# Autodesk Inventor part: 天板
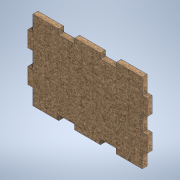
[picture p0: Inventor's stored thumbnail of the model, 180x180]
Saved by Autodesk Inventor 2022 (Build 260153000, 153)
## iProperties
Created: 2024-11
Part Number: 天板
Material: MDF 中密度繊維ボード
Document SubType Name: Modeling
Designer: shimizu
Density: 0.8 g/cm^3
Appearance: ダンボール - 段ボール紙
Author: shimizu
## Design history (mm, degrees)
sketch "スケッチ1"
  geometry: L1 (-25.119, 2.566)-(-27.619, 2.566); L2 (-27.619, 2.566)-(-27.619, -5.434); L3 (-27.619, -5.434)-(-25.119, -5.434); L4 (-25.119, -13.434)-(-27.619, -13.434); L5 (-27.619, -13.434)-(-27.619, -21.434); L6 (-27.619, -21.434)-(-25.119, -21.434); L7 (29.881, 2.566)-(32.381, 2.566); L8 (32.381, 2.566)-(32.381, -5.434); L9 (32.381, -5.434)-(29.881, -5.434); L10 (29.881, -13.434)-(32.381, -13.434); L11 (32.381, -13.434)-(32.381, -21.434); L12 (32.381, -21.434)-(29.881, -21.434); L13 (-25.119, 2.566)-(-25.119, 10.566); L14 (-25.119, -29.434)-(-25.119, -21.434); L15 (-25.119, -13.434)-(-25.119, -5.434); L16 (29.881, 10.566)-(29.881, 2.566); L17 (29.881, -5.434)-(29.881, -13.434); L18 (29.881, -21.434)-(29.881, -29.434); L19 (-4.119, -29.434)-(-4.119, -26.934); L20 (-4.119, -26.934)-(-12.119, -26.934); L21 (-12.119, -26.934)-(-12.119, -29.434); L22 (16.881, -29.434)-(16.881, -26.934); L23 (16.881, -26.934)-(8.881, -26.934); L24 (8.881, -26.934)-(8.881, -29.434); L25 (-4.119, 10.566)-(-4.119, 8.066); L26 (-4.119, 8.066)-(-12.119, 8.066); L27 (-12.119, 8.066)-(-12.119, 10.566); L28 (16.881, 10.566)-(16.881, 8.066); L29 (16.881, 8.066)-(8.881, 8.066); L30 (8.881, 8.066)-(8.881, 10.566); L31 (-25.119, 10.566)-(-12.119, 10.566); L32 (-4.119, 10.566)-(8.881, 10.566); L33 (16.881, 10.566)-(29.881, 10.566); L34 (-12.119, -29.434)-(-25.119, -29.434); L35 (29.881, -29.434)-(16.881, -29.434); L36 (8.881, -29.434)-(-4.119, -29.434); 1 further point
  constraints: 72 end point, 26 parallel, 13 perpendicular, 7 horizontal, 2 collinear
  dimensions: "d29" = 55 distance between parallel lines of L17 L15; "d30" = 35 distance between parallel lines of L20 L26; "d31" = 60 distance between parallel lines of L11 L5; "d32" = 13 distance of L21.end L14.start; "d33" = 13 distance of L24.end L19.start; "d34" = 13 distance of L18.end L22.start; "d35" = 13 distance of L13.end L27.end; "d36" = 13 distance of L25.start L30.end; "d37" = 13 distance of L28.start L16.start; "d38" = 8 distance of L28.end L29.end; "d39" = 8 distance of L25.end L26.end; "d40" = 8 distance of L22.end L23.end; "d41" = 8 distance of L19.end L20.end; "d42" = 8 distance of L9.end L10.start
extrude "押し出し1" new body sketch "スケッチ1" distance "d2" = 2.5; taper "d3" = 0 deg
node "ソリッド1"
